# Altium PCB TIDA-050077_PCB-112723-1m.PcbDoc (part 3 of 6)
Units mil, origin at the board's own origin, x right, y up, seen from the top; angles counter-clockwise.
Board outline 3780 x 7750 mil, 16 copper layers (Top Layer, L2-Powet 1, L3-Power 2, L4-Power 3, L5-Power 4, L6-INT 1, L7-INT 2, L8-INT 3, L9-INT 4, L10-INT 5, L11-INT 6, L12-Power 5, L13-Power 6, L14-Power 7, L15-Power 8, Bottom Layer), stack 121.442 mil thick; 381 components, 136 nets, 958 pads, 3470 vias.
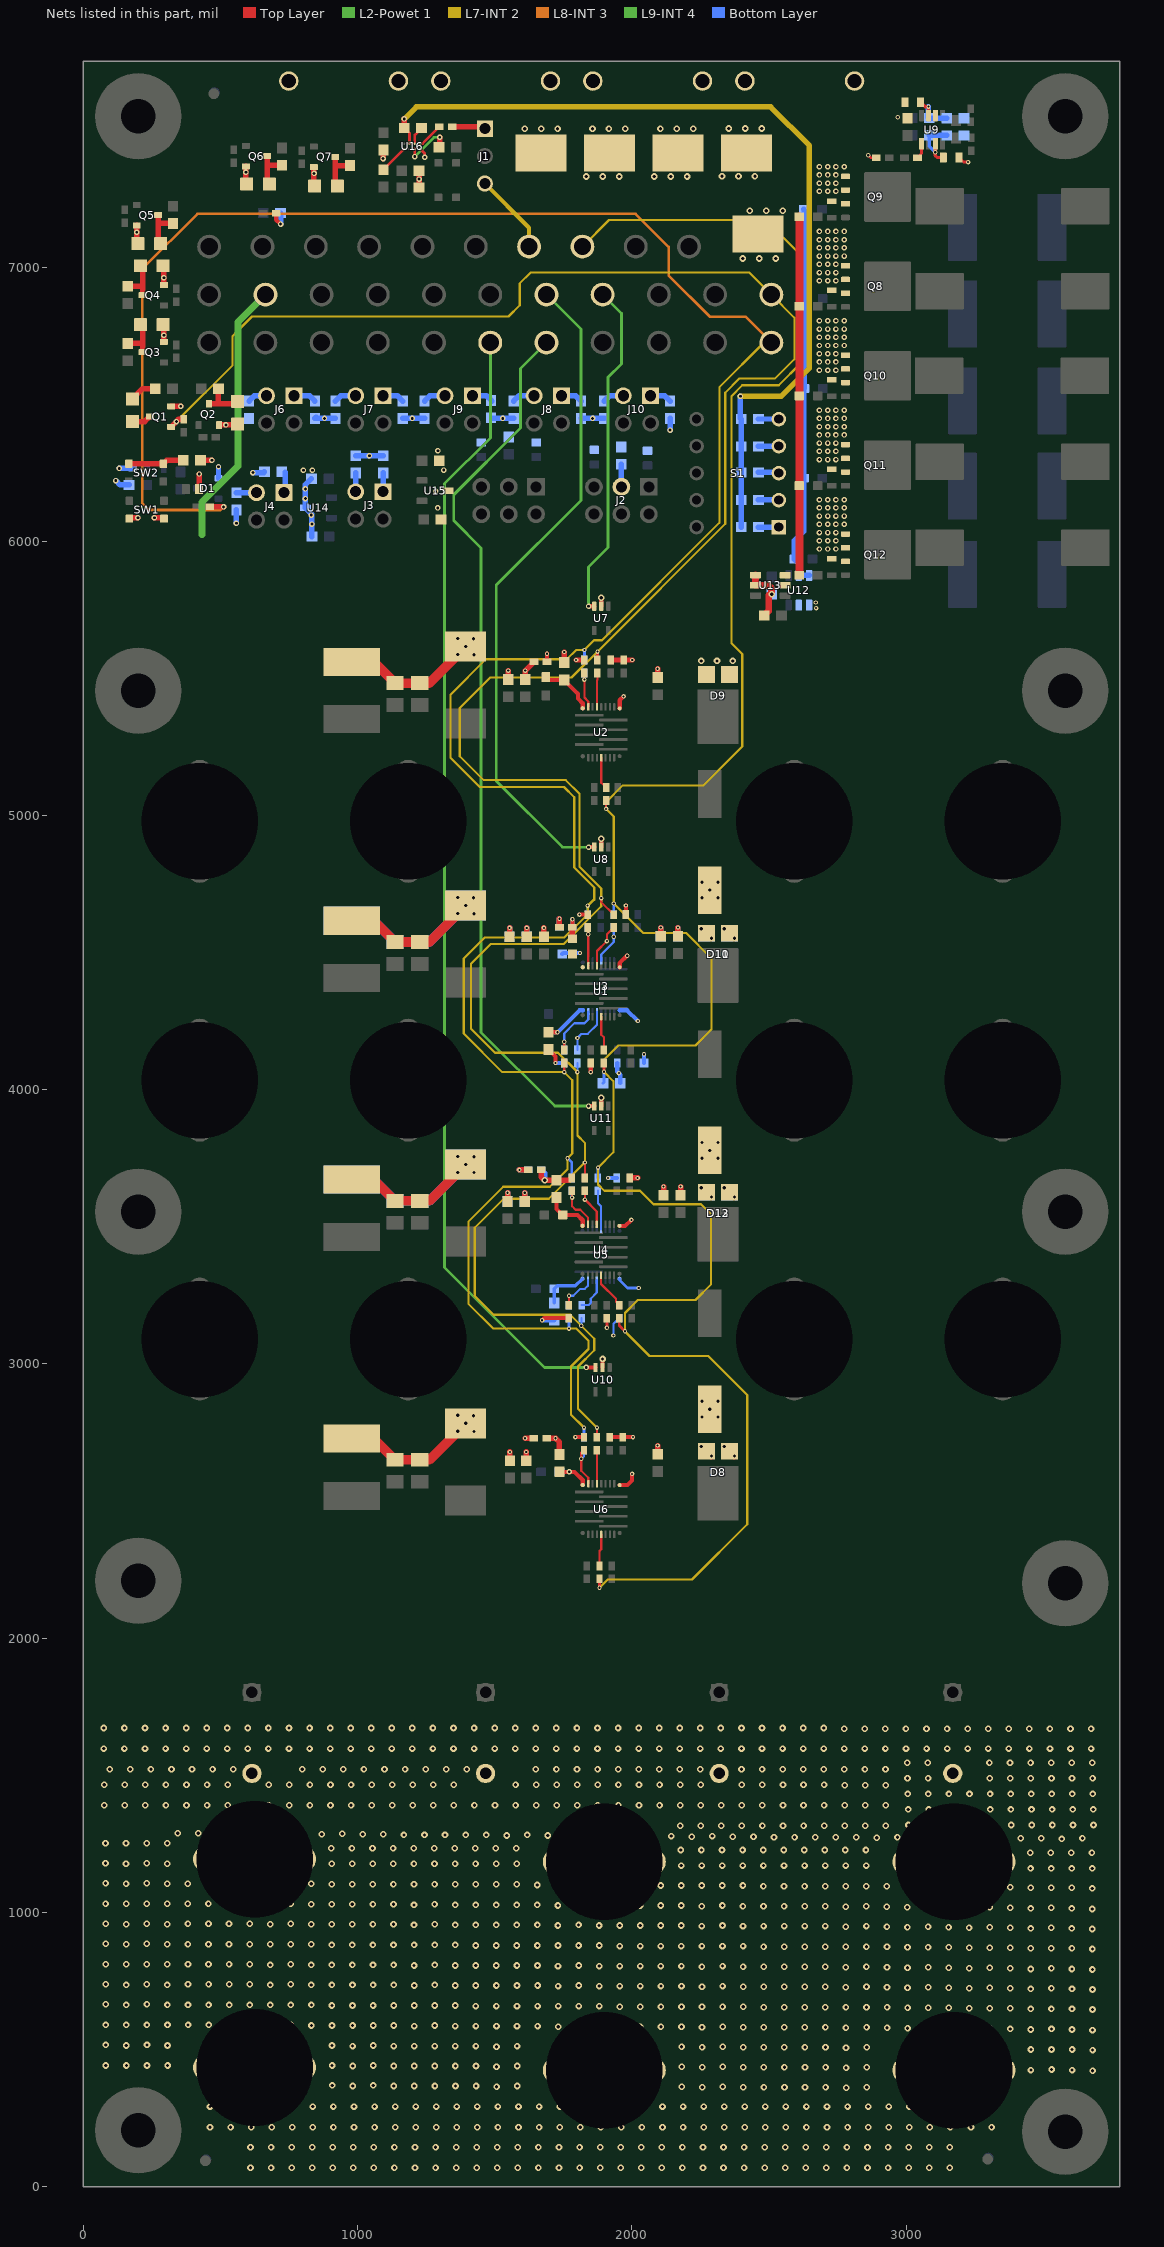
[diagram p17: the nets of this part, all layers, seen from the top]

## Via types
v1: diameter 24, hole 12, Top Layer to Bottom Layer, 2618 vias
v2: diameter 20, hole 10, Top Layer to Bottom Layer, 508 vias
v3: diameter 16, hole 8, Top Layer to Bottom Layer, tented both sides, 135 vias
v4: diameter 24, hole 12.1, Top Layer to Bottom Layer, 125 vias
v5: diameter 20, hole 10, Top Layer to Bottom Layer, tented both sides, 84 vias

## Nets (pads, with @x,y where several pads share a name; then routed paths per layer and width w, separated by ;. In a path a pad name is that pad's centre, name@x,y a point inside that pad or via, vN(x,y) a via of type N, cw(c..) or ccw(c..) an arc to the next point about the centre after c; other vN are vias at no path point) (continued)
NetCD3_1: CD3.1 J2.3 | length 82.1
  Bottom Layer w20: CD3.1@1961.46,6280.53 1961.46,6199.28 J2.3@1962.04,6198.69
NetCT1_1: CT1.1 U16.C2 | length 67.2
  Top Layer w10: U16.C2@1208.73,7449.78 1208.73,7482 CT1.1@1233.45,7506.72
NetCT1_2: CT1.2 R52.1 R53.1 R56.1 R57.1 R58.1 U16.B2 | length 3234.4
  Top Layer w10: CT1.2@1170.46,7506.72 1189.04,7488.14 U16.B2@1189.04,7449.78
  Top Layer w20: CT1.2@1170.46,7506.72 v5(1170.46,7540.09)
  L7-INT 2 w20: v5(1170.46,7540.09) 1214.27,7583.9 2505.86,7583.9 2647.06,7442.69 2647.06,6631.08 2544.42,6528.44 v5(2395.98,6528.44)
  Bottom Layer w20: v5(2395.98,6528.44) 2395.98,6448.59 R58.1@2398.73,6445.84 R57.1@2398.73,6345.84 R56.1@2398.73,6250.84 R53.1@2398.73,6150.84 R52.1@2398.73,6051.59
NetDG1_1: DG1.1 Q1.3 | length 71.2
  Top Layer w20: DG1.1@178.48,6436.38 223.7,6436.38 Q1.3@242.08,6454.76
NetDG1_2: DG1.2 R8.1 | length 99
  Top Layer w20: DG1.2@178.48,6519.06 215.98,6556.56 R8.1@261.98,6556.56
NetDR1_2: DR1.2 Q2.3 R9.2 | length 161.7
  Top Layer w20: Q2.3@458.98,6502.28 490.09,6502.28 ; R9.2@492.58,6556.19 492.58,6504.77 490.09,6502.28 ; DR1.2@562.48,6510.14 554.62,6502.28 490.09,6502.28
NetDR2_2: DR2.2 Q3.3 R7.2 | length 157.2
  Top Layer w20: R7.2@162.04,6721.26 215.83,6721.26 215.95,6721.37 ; DR2.2@208.09,6789.76 215.95,6781.9 215.95,6721.37 ; Q3.3@215.95,6689.76 215.95,6721.37
NetDR3_2: DR3.2 Q4.3 R1.2 | length 165.3
  Top Layer w20: R1.2@162.04,6929.76 214.34,6929.76 215.95,6931.37 ; DR3.2@208.09,7004.76 215.95,6996.9 215.95,6931.37 ; Q4.3@215.95,6897.26 215.95,6931.37
NetDR4_2: DR4.2 Q5.3 R2.2 | length 162.4
  Top Layer w20: Q5.3@272.66,7189.27 272.66,7161.42 ; DR4.2@281.48,7085.43 272.66,7094.25 272.66,7161.42 ; R2.2@326.57,7158.93 275.15,7158.93 272.66,7161.42
NetDR5_2: DR5.2 Q6.3 R3.2 | length 161.1
  Top Layer w20: Q6.3@670.46,7404.33 670.46,7376.01 ; DR5.2@678.32,7302.35 670.46,7310.21 670.46,7376.01 ; R3.2@724.38,7371.19 675.28,7371.19 670.46,7376.01
NetDR6_2: DR6.2 Q7.3 R4.2 | length 164.5
  Top Layer w20: Q7.3@918.47,7401.46 918.47,7368.23 ; DR6.2@926.33,7294.84 918.47,7302.7 918.47,7368.23 ; R4.2@972.38,7369.96 920.2,7369.96 918.47,7368.23
NetJ1_1: J1.1 RZ4.2 | length 121.7
  Top Layer w20: RZ4.2@1345.58,7511.72 1456.96,7511.72 J1.1@1464.28,7504.41
NetJ1_3: J1.3 TP8.1 | length 296.6
  L7-INT 2 w15: J1.3@1464.28,7304.41 1625.4,7143.29 TP8.1@1625.4,7074.5
NetJ3_1: J3.1 r51.2 | length 68.5
  Bottom Layer w20: J3.1@1093.21,6180.62 r51.2@1093.21,6249.13
NetJ3_3: J3.3 R54.2 | length 68.5
  Bottom Layer w20: J3.3@993.21,6180.62 R54.2@993.21,6249.13
NetJ4_1: J4.1 RL1.2 | length 76.2
  Bottom Layer w20: J4.1@731.41,6177.18 735.57,6181.34 RL1.2@735.57,6251.65
NetJ4_3: J4.3 RL2.2 | length 73.2
  Bottom Layer w20: RL2.2@558.21,6177.18 J4.3@631.41,6177.18
NetJ6_1: J6.1 R61.2 | length 79.9
  Bottom Layer w20: J6.1@772.53,6530.62 824.7,6530.62 R61.2@844.33,6510.99
NetJ6_3: J6.3 R62.2 | length 76.3
  Bottom Layer w20: R62.2@604.33,6510.99 623.96,6530.62 J6.3@672.53,6530.62
NetJ7_1: J7.1 R66.2 | length 79.3
  Bottom Layer w20: J7.1@1093.21,6530.62 1144.7,6530.62 R66.2@1164.33,6510.99
NetJ7_3: J7.3 R67.2 | length 82
  Bottom Layer w20: R67.2@919.33,6510.99 938.96,6530.62 J7.3@993.21,6530.62
NetJ8_1: J8.1 R71.2 | length 79.3
  Bottom Layer w20: J8.1@1743.66,6530.62 1795.18,6530.62 R71.2@1814.81,6510.99
NetJ8_3: J8.3 R72.2 | length 82.5
  Bottom Layer w20: R72.2@1569.33,6510.99 1588.96,6530.62 J8.3@1643.66,6530.62
NetJ9_1: J9.1 R76.2 | length 79
  Bottom Layer w20: J9.1@1418.43,6530.62 1469.7,6530.62 R76.2@1489.33,6510.99
NetJ9_3: J9.3 R77.2 | length 82.2
  Bottom Layer w20: R77.2@1244.33,6510.99 1263.96,6530.62 J9.3@1318.43,6530.62
NetJ10_1: J10.1 R81.2 | length 78.6
  Bottom Layer w20: J10.1@2068.88,6530.62 2119.7,6530.62 R81.2@2139.33,6510.99
NetJ10_3: J10.3 R82.2 | length 78.2
  Bottom Layer w20: R82.2@1898.82,6510.99 1918.45,6530.62 J10.3@1968.88,6530.62
NetR18_1: R18.1 R19.1 R20.1 R21.1 R22.1 U12.2 U12.3 | length 1396
  Bottom Layer w20: R19.1@2626.85,7210.5 2628.82,7208.52 R18.1@2628.82,6885.07 2629.63,6884.27 R20.1@2629.63,6557.06 2627.73,6555.16 R21.1@2627.73,6230.06 2627.73,6036.96 2592.06,6001.3 R22.1@2592.06,5935.11 2608.8,5918.37 U12.2@2608.8,5875.52 U12.3@2646.21,5875.52
NetR33_1: R33.1 R34.1 R35.1 R36.1 R37.1 U13.2 U13.3 | length 1307.1
  Top Layer w29.53: R37.1@2610.86,5876.37 R36.1@2610.86,6203.15 R35.1@2610.86,6529.93 R33.1@2610.86,6856.72 R34.1@2610.86,7183.5
NetR38_1: R38.1 U16.A1 | length 99.4
  Top Layer w10: R38.1@1099.85,7359.48 1099.85,7360.59 U16.A1@1169.36,7430.09
NetR39_1: R39.1 U16.C1 | length 184.7
  Top Layer w10: v5(1208.73,7403.01) U16.C1@1208.73,7430.09
  Top Layer w20: R39.1@1296.96,7436.72 1299.85,7439.62 v5(1299.85,7472.98)
  L9-INT 4 w10: v5(1208.73,7403.01) 1278.7,7472.98 v5(1299.85,7472.98)
NetR48_1: R48.1 SW2.1 SW2.2 | length 203.2
  Top Layer w20: SW2.1@166.03,6282.78 SW2.2@292.01,6282.78 304.53,6295.3 R48.1@364.02,6295.3
NetR52_2: R52.2 S1.1 | length 73.1
  Bottom Layer w20: R52.2@2461.72,6051.59 S1.1@2534.79,6051.59
NetR53_2: R53.2 S1.2 | length 73.4
  Bottom Layer w20: R53.2@2461.72,6150.84 2533.97,6150.84 S1.2@2534.79,6150.01
NetR56_2: R56.2 S1.3 | length 74.1
  Bottom Layer w20: R56.2@2461.72,6250.84 2532.39,6250.84 S1.3@2534.79,6248.44
NetR57_2: R57.2 S1.4 | length 73.5
  Bottom Layer w20: R57.2@2461.72,6345.84 2533.76,6345.84 S1.4@2534.79,6346.86
NetR58_2: R58.2 S1.5 | length 73.3
  Bottom Layer w20: R58.2@2461.72,6445.84 2534.24,6445.84 S1.5@2534.79,6445.29
NetRZ2_2: RZ2.2 U9.5 | length 63.1
  Top Layer w10: RZ2.2@3036.82,7394.6 3056.24,7414.02 U9.5@3056.24,7449.64
NetRZ4_1: RZ4.1 U16.D2 | length 95.6
  Top Layer w10: U16.D2@1228.41,7449.78 1236.39,7449.78 RZ4.1@1298.33,7511.72
NetTP1_1: TP1.1 U7.3 | length 1235.2
  Top Layer w15: v5(1842.12,5763.19) U7.3@1863.04,5763.19
  L9-INT 4 w10: v5(1842.12,5763.19) 1842.12,5906.36 1913.42,5977.67 1913.42,6598.04 1962.04,6646.66 1962.04,6831.18 TP1.1@1893.73,6899.5
NetTP2_1: TP2.1 U8.3 | length 2411
  Top Layer w15: v5(1842.12,4884.52) U8.3@1863.04,4884.52
  L9-INT 4 w10: TP2.1@1688.73,6899.5 1814.28,6773.95 1814.28,6148.5 1505.65,5839.87 1505.65,5125.55 1746.67,4884.52 v5(1842.12,4884.52)
NetTP3_1: TP3.1 U10.3 | length 4143.9
  Top Layer w15: v5(1833.56,2987.29) U10.3@1867.8,2987.29
  L9-INT 4 w10: TP3.1@1483.73,6724.5 1484.28,6723.95 1484.28,6377.15 1317.13,6210 1317.13,3351.6 1681.44,2987.29 v5(1833.56,2987.29)
NetTP4_1: TP4.1 U11.3 | length 3220.5
  Top Layer w15: v5(1842.12,3940.33) U11.3@1863.04,3940.33
  L9-INT 4 w10: TP4.1@1688.73,6724.5 1594.28,6630.05 1594.28,6413.11 1350.77,6169.59 1350.77,6075.08 1450.31,5975.54 1450.31,4209.42 1719.4,3940.33 v5(1842.12,3940.33)
PG: Q1.1 R44.2 RZ10.2 RZ17.2 RZ24.2 RZ31.2 RZ38.2 RZ45.2 TP17.1 | length 9486.6
  Top Layer w8: RZ31.2@1828.77,3678.28 v3(1828.77,3734.42) ; RZ45.2@1872.89,2733.08 v3(1872.89,2767.89) ; v3(1888.63,4698.9) 1888.63,4684.13 RZ10.2@1934.13,4638.63
  Top Layer w12: RZ17.2@1874.76,5567.04 v3(1874.76,5597.49)
  Top Layer w20: Q1.1@320.09,6417.26 v5(339.21,6436.38) 347.72,6444.89 R44.2@366.08,6444.89
  L7-INT 2 w8: v5(339.21,6436.38) 544.28,6641.45 544.28,6748.83 614.73,6819.28 1550.12,6819.28 1591.63,6860.79 1591.63,6940.45 1631.43,6980.25 2427.98,6980.25 TP17.1@2508.73,6899.5 2592.67,6815.55 2592.67,6664.02 2522.55,6593.9 2392.84,6593.9 2340.77,6541.82 2340.77,6063.5 v3(1874.76,5597.49) 1780.13,5502.86 1483.64,5502.86 1372.57,5391.79 1372.57,5216.14 1459.81,5128.9 1759.28,5128.9 1809.66,5078.52 1809.66,4812.52 1888.63,4733.55 v3(1888.63,4698.9) 1888.63,4668.73 1751.57,4531.67 1485.55,4531.67 1413.58,4459.7 1413.58,4222.8 1501.24,4135.13 1730.84,4135.13 v3(1801.66,4064.31) 1801.66,3833.32 1828.77,3806.21 v3(1828.77,3734.42) 1696.78,3602.43 1533.29,3602.43 1427.22,3496.36 1427.22,3248.12 1495.8,3179.54 1775.38,3179.54 v3(1815.91,3139) 1862.98,3091.94 1862.98,3049.77 1803.99,2990.78 1803.99,2836.78 v3(1872.89,2767.89)
  Bottom Layer w8: v3(1801.66,4064.31) RZ24.2@1801.66,4097.6 ; v3(1815.91,3139) 1816.55,3139.63 RZ38.2@1816.55,3167.28
PG_0: RZ10.1 U1.19 | length 165
  Top Layer w7.87: U1.19@1872.89,4451.8 1872.89,4505.77 v3(1909.07,4541.95) 1909.07,4566.33 RZ10.1@1934.13,4591.39
PG_1: RZ17.1 U2.19 | length 124.6
  Top Layer w8: U2.19@1872.89,5396 1872.89,5493.55 1874.76,5495.42 RZ17.1@1874.76,5519.8
PG_2: RZ24.1 U3.19 | length 182.3
  Bottom Layer w8: RZ24.1@1801.66,4144.84 v3(1801.66,4188.72) 1816.51,4203.57 1838.98,4203.57 1872.89,4237.47 U3.19@1872.89,4284.48
PG_3: RZ31.1 U4.19 | length 140.2
  Top Layer w8: RZ31.1@1828.77,3631.03 1828.77,3599.68 v3(1829.02,3599.42) 1872.19,3556.26 U4.19@1872.19,3508.81
PG_4: RZ38.1 U5.19 | length 129.5
  Bottom Layer w8: RZ38.1@1816.55,3214.52 1842.28,3214.52 1850.05,3222.3 1850.05,3238.26 1872.19,3260.4 U5.19@1872.19,3305.85
PG_5: RZ45.1 U6.19 | length 122.5
  Top Layer w8: U6.19@1872.89,2563.41 1872.89,2598.6 1872.83,2598.6 1872.83,2632.5 1872.89,2632.56 RZ45.1@1872.89,2685.83
PGND: C6.2 C7.2 C10.1 C11.1 C12.1 C13.1 C14.1 C19.2 C20.2 C21.2 C22.2 C23.2 C24.2 C31.2 C32.2 C33.2 C34.2 C35.2 C36.2 C37.2 C38.2 C39.2 C40.2 C41.2 C42.2 C43.2 C44.2 C45.2 C46.2 C47.2 C48.2 C49.2 C50.2 C51.2 C53.2 C54.2 C55.2 C57.2 C58.2 C59.2 C61.2 C62.2 C63.2 C65.2 C66.2 C67.2 CO1.2 CO2.2 CO3.2 CO4.2 CO5.2 CO6.2 CO7.2 D2.2 D3.2 D4.2 D5.2 D6.2 D7.2 D8.1 D8.2 D9.1 D9.2 D10.1 D10.2 D11.1 D11.2 D12.1 D12.2 D13.1 D13.2 Q8.1 Q8.2 Q8.3 Q9.1 Q9.2 Q9.3 Q10.1 Q10.2 Q10.3 Q11.1 Q11.2 Q11.3 Q12.1 Q12.2 Q12.3 RZ5.2 RZ13.2 RZ20.2 RZ27.2 RZ34.2 RZ41.2 T3.1 T4.1 T11.1 T12.1 T13.1 T16.1 T17.1 TP15.1 U12.4 U12.5 U13.4 U13.5 | length 5426.3
  Top Layer w20: C62.2@1547.08,3592.68 v3(1547.08,3624.63) ; C49.2@1549.28,5496.22 v3(1549.28,5528.18) ; C21.2@1554.28,4558 v3(1554.28,4589.96) ; C65.2@1555.44,2647.15 v3(1555.44,2679.1) ; v3(1589.89,3707.77) RZ27.2@1621.84,3707.77 ; C58.2@1609.26,3592.68 v3(1609.26,3624.63) ; v3(1610.74,2728.9) RZ41.2@1642.69,2728.9 ; C50.2@1611.52,5496.22 v3(1611.52,5528.18) ; C50.2@1611.52,5513.02 v3(1611.52,5528.18) ; C66.2@1615.01,2647.15 v3(1615.01,2679.1) ; C19.2@1616.81,4558 v3(1616.81,4589.96) ; RZ13.2@1643.24,5559.9 v3(1611.52,5528.18) ; C20.2@1679.34,4558 v3(1679.34,4589.96) ; RZ5.2@1736.1,4591.62 v3(1736.1,4623.58) ; C67.2@2094.18,2670.48 v3(2094.18,2702.43) ; C51.2@2094.18,5503.07 v3(2094.18,5535.02) ; C23.2@2105.75,4559.42 v3(2105.75,4591.37) ; C59.2@2115.7,3615.05 v3(2115.7,3647) ; C24.2@2168.28,4559.42 v3(2168.28,4591.37) ; C63.2@2177.9,3615.05 v3(2177.9,3647)
  Top Layer w25: v1(2253.44,2698.63) 2270.41,2681.66 D8.1@2272.35,2681.66 D8.1@2289.69,2664.32 ; v1(2253.44,3642.83) 2270.41,3625.85 D13.1@2272.35,3625.85 D13.1@2289.69,3608.51 ; v1(2253.44,4587.02) 2270.41,4570.05 D11.1@2272.35,4570.05 D11.1@2289.69,4552.71 ; v1(2337.29,2698.63) 2354.27,2681.66 D8.2@2356.21,2681.66 D8.2@2373.55,2664.32 ; v1(2337.29,3642.83) 2354.27,3625.85 D13.2@2356.21,3625.85 D13.2@2373.55,3608.51 ; v1(2337.29,4587.02) 2354.27,4570.05 D11.2@2356.21,4570.05 D11.2@2373.55,4552.71 ; U13.4@2450.85,5876.89 U13.5@2450.85,5839.49 2499.24,5839.49 2509.28,5829.46 2509.28,5812.13 2499.24,5802.1 2499.24,5745.91 C7.2@2482.83,5729.5
  Top Layer w35: C42.2@978.28,2739.6 1047.35,2739.6 C45.2@1136.71,2650.25 C46.2@1226.71,2650.25 1261.78,2650.25 v1(1365.72,2754.18) 1365.72,2755.17 v1(1393.92,2783.37) ; C33.2@978.28,3683.8 1047.35,3683.8 C39.2@1136.71,3594.44 1261.78,3594.44 v1(1365.72,3698.38) 1365.72,3699.37 v1(1393.92,3727.57) ; C32.2@978.28,4627.99 1047.35,4627.99 C37.2@1136.71,4538.64 1261.78,4538.64 v1(1365.72,4642.57) 1365.72,4643.57 v1(1393.92,4671.77) ; C31.2@978.28,5572.19 1047.35,5572.19 C35.2@1136.71,5482.83 1261.78,5482.83 v1(1365.72,5586.77) 1365.72,5587.76 v1(1393.92,5615.96)
  L2-Powet 1 w25: 432.86,6023.9 432.86,6142.4 564.08,6273.62 564.08,6799.36 TP15.1@664.22,6899.5
  Bottom Layer w20: C61.2@1547.08,3592.68 v3(1547.08,3624.63) ; C54.2@1554.28,4558 v3(1554.28,4589.96) ; v3(1589.89,3707.77) RZ34.2@1621.84,3707.77 ; C57.2@1609.26,3592.68 v3(1609.26,3624.63) ; C53.2@1616.81,4558 v3(1616.81,4589.96) ; RZ20.2@1736.1,4591.62 v3(1736.1,4623.58) ; C22.2@2105.75,4559.42 v3(2105.75,4591.37) ; C55.2@2168.28,4559.42 v3(2168.28,4591.37)
  Bottom Layer w35: C40.2@978.28,3683.8 1047.35,3683.8 C43.2@1136.71,3594.44 1261.78,3594.44 v1(1365.72,3698.38) 1365.72,3699.37 v1(1393.92,3727.57) ; C41.2@978.28,4627.99 1047.35,4627.99 C47.2@1136.71,4538.64 1261.79,4538.64 v1(1365.72,4642.57) 1365.72,4643.57 v1(1393.92,4671.77)
  other v1: 609.42,68.9 684.42,68.9 759.42,68.9 834.42,68.9 909.42,68.9 984.42,68.9 1059.42,68.9 1134.42,68.9 1209.42,68.9 1284.42,68.9 1359.42,68.9 1434.42,68.9 1509.42,68.9 1584.42,68.9 1659.42,68.9 1734.42,68.9 1809.43,68.9 1884.43,68.9 1959.43,68.9 2034.43,68.9 2109.43,68.9 2184.43,68.9 2259.43,68.9 2334.43,68.9 2409.43,68.9 2484.43,68.9 2559.43,68.9 2634.43,68.89 2709.43,68.89 2784.43,68.89 2859.43,68.89 2934.43,68.89 3009.43,68.89 3084.43,68.89 3159.43,68.89 609.42,143.9 684.42,143.9 759.42,143.9 834.42,143.9 909.42,143.9 984.42,143.9 1059.42,143.9 1134.42,143.9 1209.42,143.9 1284.42,143.9 1359.42,143.9 1434.42,143.9 1509.42,143.9 1584.42,143.9 1659.42,143.9 1734.42,143.9 1809.42,143.9 1884.43,143.9 1959.43,143.9 2034.43,143.9 2109.43,143.9 2184.43,143.9 2259.43,143.9 2334.43,143.9 2409.43,143.9 2484.43,143.9 2559.43,143.9 2634.43,143.89 2709.43,143.89 2784.43,143.89 2859.43,143.89 2934.43,143.89 3009.43,143.89 3084.43,143.89 3159.43,143.89 461.82,216.87 536.82,216.87 611.82,216.87 686.83,216.87 761.83,216.87 836.83,216.87 911.83,216.87 986.83,216.87 1061.83,216.87 1136.83,216.87 1211.83,216.87 1286.83,216.87 1361.83,216.87 1436.83,216.87 1511.83,216.87 1586.83,216.87 1661.83,216.87 1736.83,216.87 1811.83,216.87 1886.83,216.87 1961.83,216.87 2036.83,216.87 2111.83,216.87 2186.83,216.87 2261.83,216.87 2336.83,216.87 2411.83,216.87 2486.83,216.87 2561.83,216.87 2636.83,216.87 2711.83,216.87 2786.83,216.87 2861.83,216.87 2936.83,216.87 3011.83,216.87 3086.83,216.87 3161.83,216.87 3236.83,216.87 3311.83,216.87 461.82,291.87 536.82,291.87 611.82,291.87 686.82,291.87 761.83,291.87 836.83,291.87 911.83,291.87 986.83,291.87 1061.83,291.87 1136.83,291.87 1211.83,291.87 1286.83,291.87 1361.83,291.87 1436.83,291.87 1511.83,291.87 1586.83,291.87 1661.83,291.87 1736.83,291.87 1811.83,291.87 1886.83,291.87 1961.83,291.87 2036.83,291.87 2111.83,291.87 2186.83,291.87 2261.83,291.87 2336.83,291.87 2411.83,291.87 2486.83,291.87 2561.83,291.87 2636.83,291.87 2711.83,291.87 2786.83,291.87 2861.83,291.87 2936.83,291.87 3011.83,291.87 3086.83,291.87 3161.83,291.87 3236.83,291.87 3311.83,291.87 2781.43,360.57 2256.62,362.67 2406.62,362.67 2481.62,362.67 2556.62,362.67 2631.62,362.67 2706.62,362.67 2856.63,362.67 1506.82,364.77 2181.82,364.77 2331.82,364.77 982.02,366.87 1132.02,366.87 1207.02,366.87 1282.02,366.87 1357.02,366.87 1432.02,366.87 1582.02,366.87 907.22,368.97 1057.22,368.97 3680.23,422.98 3455.43,425.08 3605.43,425.08 3530.63,427.18 2781.23,433.47 2256.42,435.57 2406.42,435.57 2481.42,435.57 2556.42,435.57 2631.43,435.57 2706.43,435.57 2856.43,435.57 1506.62,437.67 2181.62,437.67 2331.62,437.67 981.82,439.77 1131.82,439.77 1206.82,439.77 1281.82,439.77 1356.82,439.77 1431.82,439.77 1581.82,439.77 82.02,441.87 157.02,441.87 232.02,441.87 307.02,441.87 907.02,441.87 1057.02,441.87 3680.23,497.98 3455.43,500.08 3530.43,500.08 3605.43,500.08 2781.03,506.37 2256.22,508.47 2406.22,508.47 2481.22,508.47 2556.23,508.47 2631.23,508.47 2706.23,508.47 2856.23,508.47 1506.42,510.57 2181.42,510.57 2331.42,510.57 981.62,512.67 1131.62,512.67 1206.62,512.67 1281.62,512.67 1356.62,512.67 1431.62,512.67 1581.62,512.67 156.82,514.77 306.82,514.77 906.82,514.77 1056.82,514.77 82.02,516.87 232.02,516.87 3680.03,570.88 3455.23,572.98 3605.23,572.98 3230.43,575.08 3380.43,575.08 3530.43,575.08 3005.63,577.18 3155.63,577.18 3305.63,577.18 2780.83,579.27 2930.83,579.27 3080.83,579.28 2256.02,581.37 2406.02,581.37 2481.02,581.37 2556.03,581.37 2631.03,581.37 2706.03,581.37 2856.03,581.37 1731.22,583.47 1881.22,583.47 1956.22,583.47 2031.22,583.47 2106.22,583.47 2181.22,583.47 2331.22,583.47 1206.42,585.57 1356.42,585.57 1431.42,585.57 1506.42,585.57 1581.42,585.57 1656.42,585.57 1806.42,585.57 681.62,587.67 831.62,587.67 906.62,587.67 981.62,587.67 1056.62,587.67 1131.62,587.67 1281.62,587.67 81.82,589.77 156.82,589.77 231.82,589.77 306.82,589.77 381.82,589.77 456.82,589.77 531.82,589.77 606.82,589.77 756.82,589.77 3680.03,645.88 3455.23,647.98 3530.23,647.98 3605.23,647.98 3230.43,650.08 3305.43,650.08 3380.43,650.08 3005.63,652.18 3080.63,652.18 3155.63,652.18 2480.83,654.27 2555.83,654.27 2630.83,654.27 2705.83,654.27 2780.83,654.27 2855.83,654.27 2930.83,654.27 1956.02,656.37 2031.02,656.37 2106.02,656.37 2181.02,656.37 2256.02,656.37 2331.02,656.37 2406.02,656.37 1431.22,658.47 1506.22,658.47 1581.22,658.47 1656.22,658.47 1731.22,658.47 1806.22,658.47 1881.22,658.47 906.42,660.57 981.42,660.57 1056.42,660.57 1131.42,660.57 1206.42,660.57 1281.42,660.57 1356.42,660.57 156.62,662.67 306.62,662.67 381.62,662.67 456.62,662.67 531.62,662.67 606.62,662.67 681.62,662.67 756.62,662.67 831.62,662.67 81.82,664.77 231.82,664.77 3679.83,718.78 3455.03,720.88 3605.03,720.88 3230.23,722.98 3380.23,722.98 3530.23,722.98 3005.43,725.08 3155.43,725.08 3305.43,725.08 2780.63,727.18 2930.63,727.18 3080.63,727.18 2255.82,729.27 2405.83,729.27 2480.83,729.27 2555.83,729.27 2630.83,729.27 2705.83,729.27 2855.83,729.27 1731.02,731.37 1881.02,731.37 1956.02,731.37 2031.02,731.37 2106.02,731.37 2181.02,731.37 2331.02,731.37 1206.22,733.47 1356.22,733.47 1431.22,733.47 1506.22,733.47 1581.22,733.47 1656.22,733.47 1806.22,733.47 156.42,735.57 306.42,735.57 681.42,735.57 831.42,735.57 906.42,735.57 981.42,735.57 1056.42,735.57 1131.42,735.57 1281.42,735.57 81.62,737.67 231.62,737.67 381.62,737.67 456.62,737.67 531.62,737.67 606.62,737.67 756.62,737.67 3679.63,791.68 3454.83,793.78 3604.83,793.78 3230.03,795.88 3380.03,795.88 3530.03,795.88 3005.23,797.98 3155.23,797.98 3305.23,797.98 2780.43,800.08 2930.43,800.08 3080.43,800.08 2255.62,802.17 2405.63,802.17 2480.63,802.17 2555.63,802.17 2630.63,802.17 2705.63,802.18 2855.63,802.18 1730.82,804.27 1880.82,804.27 1955.82,804.27 2030.82,804.27 2105.82,804.27 2180.82,804.27 2330.83,804.27 1206.02,806.37 1356.02,806.37 1431.02,806.37 1506.02,806.37 1581.02,806.37 1656.02,806.37 1806.02,806.37 681.22,808.47 831.22,808.47 906.22,808.47 981.22,808.47 1056.22,808.47 1131.22,808.47 1281.22,808.47 81.42,810.57 156.42,810.57 231.42,810.57 306.42,810.57 381.42,810.57 456.42,810.57 531.42,810.57 606.42,810.57 756.42,810.57 3679.63,866.68 3454.83,868.78 3529.83,868.78 3604.83,868.78 3230.03,870.88 3305.03,870.88 3380.03,870.88 3005.23,872.98 3080.23,872.98 3155.23,872.98 2480.43,875.08 2555.43,875.08 2630.43,875.08 2705.43,875.08 2780.43,875.08 2855.43,875.08 2930.43,875.08 1955.62,877.17 2030.62,877.17 2105.62,877.17 2180.62,877.17 2255.63,877.17 2330.63,877.17 2405.63,877.17 1430.82,879.27 1505.82,879.27 1580.82,879.27 1655.82,879.27 1730.82,879.27 1805.82,879.27 1880.82,879.27 906.02,881.37 981.02,881.37 1056.02,881.37 1131.02,881.37 1206.02,881.37 1281.02,881.37 1356.02,881.37 156.22,883.47 306.22,883.47 381.22,883.47 456.22,883.47 531.22,883.47 606.22,883.47 681.22,883.47 756.22,883.47 831.22,883.47 81.42,885.57 231.42,885.57 3679.43,939.58 3454.63,941.68 3604.63,941.68 3229.83,943.78 3379.83,943.78 3529.83,943.78 3005.03,945.88 3155.03,945.88 3305.03,945.88 2780.23,947.98 2930.23,947.98 3080.23,947.98 2255.43,950.07 2405.43,950.08 2480.43,950.08 2555.43,950.08 2630.43,950.08 2705.43,950.08 2855.43,950.08 1730.62,952.17 1880.62,952.17 1955.62,952.17 2030.62,952.17 2105.62,952.17 2180.63,952.17 2330.63,952.17 1205.82,954.27 1355.82,954.27 1430.82,954.27 1505.82,954.27 1580.82,954.27 1655.82,954.27 1805.82,954.27 156.02,956.37 306.02,956.37 681.02,956.37 831.02,956.37 906.02,956.37 981.02,956.37 1056.02,956.37 1131.02,956.37 1281.02,956.37 81.22,958.47 231.22,958.47 381.22,958.47 456.22,958.47 531.22,958.47 606.22,958.47 756.22,958.47 3679.23,1012.48 3454.43,1014.58 3604.43,1014.58 3229.63,1016.68 3379.63,1016.68 3529.63,1016.68 3004.83,1018.78 3154.83,1018.78 3304.83,1018.78 2780.03,1020.88 2930.03,1020.88 3080.03,1020.88 2255.23,1022.98 2405.23,1022.98 2480.23,1022.98 2555.23,1022.98 2630.23,1022.98 2705.23,1022.98 2855.23,1022.98 1730.42,1025.07 1880.42,1025.07 1955.42,1025.07 2030.43,1025.07 2105.43,1025.07 2180.43,1025.07 2330.43,1025.07 1205.62,1027.17 1355.62,1027.17 1430.62,1027.17 1505.62,1027.17 1580.62,1027.17 1655.62,1027.17 1805.62,1027.17 680.82,1029.27 830.82,1029.27 905.82,1029.27 980.82,1029.27 1055.82,1029.27 1130.82,1029.27 1280.82,1029.27 81.02,1031.37 156.02,1031.37 231.02,1031.37 306.02,1031.37 381.02,1031.37 456.02,1031.37 531.02,1031.37 606.02,1031.37 756.02,1031.37 3679.23,1087.48 3454.43,1089.58 3529.43,1089.58 3604.43,1089.58 3229.63,1091.68 3304.63,1091.68 3379.63,1091.68 3004.83,1093.78 3079.83,1093.78 3154.83,1093.78 2480.03,1095.88 2555.03,1095.88 2630.03,1095.88 2705.03,1095.88 2780.03,1095.88 2855.03,1095.88 2930.03,1095.88 1955.23,1097.97 2030.23,1097.97 2105.23,1097.98 2180.23,1097.98 2255.23,1097.98 2330.23,1097.98 2405.23,1097.98 1655.42,1100.07 1730.42,1100.07 1805.42,1100.07 1880.42,1100.07 905.62,1102.17 980.62,1102.17 1055.62,1102.17 1130.62,1102.17 1205.62,1102.17 1280.62,1102.17 1355.62,1102.17 1430.42,1102.17 1505.42,1102.17 1580.42,1102.17 155.82,1104.27 305.82,1104.27 380.82,1104.27 455.82,1104.27 530.82,1104.27 605.82,1104.27 680.82,1104.27 755.82,1104.27 830.82,1104.27 81.02,1106.37 231.02,1106.37 3454.03,1160.38 3529.03,1160.38 3604.03,1160.38 3679.03,1160.38 2180.03,1170.88 2255.03,1170.88 2330.03,1170.88 2405.03,1170.88 2480.03,1170.88 2555.03,1170.88 2630.03,1170.88 2704.83,1170.88 2779.83,1170.88 2854.83,1170.88 155.62,1177.17 305.62,1177.17 905.42,1177.17 980.42,1177.17 1055.42,1177.17 1130.42,1177.17 1205.42,1177.17 1280.42,1177.17 1355.42,1177.17 1430.22,1177.17 1505.22,1177.17 1580.22,1177.17 80.82,1179.27 230.82,1179.27 3452.88,1217.1 3527.88,1217.1 3602.88,1217.1 3677.88,1217.1 2178.88,1227.6 2253.88,1227.6 2328.88,1227.6 2403.88,1227.6 2478.88,1227.6 2553.88,1227.6 2628.88,1227.6 2703.68,1227.6 2778.68,1227.6 2853.68,1227.6 904.28,1233.9 979.28,1233.9 1054.28,1233.9 1129.28,1233.9 1204.28,1233.9 1279.28,1233.9 1354.28,1233.9 1429.08,1233.9 1504.08,1233.9 1579.08,1233.9 80.62,1252.17 155.62,1252.17 230.62,1252.17 305.62,1252.17 3568.09,1267.91 3193.29,1270 3268.29,1270 3343.29,1270 3418.29,1270 3493.29,1270 3643.29,1270 2893.28,1272.1 3043.29,1272.1 3118.49,1272.1 2518.48,1274.2 2593.48,1274.2 2668.48,1274.2 2743.48,1274.2 2818.48,1274.2 2968.49,1274.2 2218.48,1276.3 2368.48,1276.3 2443.68,1276.3 1843.68,1278.4 1918.68,1278.4 1993.68,1278.4 2068.68,1278.4 2143.68,1278.4 2293.68,1278.4 1543.68,1280.5 1693.68,1280.5 1768.88,1280.5 1168.88,1282.6 1243.88,1282.6 1318.88,1282.6 1393.88,1282.6 1468.88,1282.6 1618.88,1282.6 868.88,1284.7 1018.88,1284.7 1094.08,1284.7 494.08,1286.8 569.08,1286.8 644.08,1286.8 719.08,1286.8 794.08,1286.8 944.08,1286.8 344.08,1288.9 419.28,1288.9 2176.35,1315.62 2251.35,1315.62 2326.35,1315.62 2401.35,1315.62 2476.35,1315.62 2551.35,1315.62 2626.35,1315.62 2701.35,1315.62 2776.35,1315.62 2851.35,1315.62 2926.35,1315.62 3008.69,1318.71 3083.69,1318.71 3158.69,1318.71 3233.69,1318.71 3308.69,1318.71 3383.69,1318.71 3458.69,1318.71 3533.69,1318.71 3608.69,1318.71 3683.49,1318.71 3007.54,1375.43 3082.54,1375.43 3157.54,1375.43 3232.54,1375.43 3307.54,1375.43 3382.54,1375.43 3457.54,1375.43 3532.54,1375.43 3607.54,1375.43 3682.34,1375.43 76.15,1390.62 151.15,1390.62 226.15,1390.62 301.15,1390.62 376.15,1390.62 451.15,1390.62 526.15,1390.62 601.15,1390.62 676.15,1390.62 751.15,1390.62 826.15,1390.62 901.15,1390.62 976.15,1390.62 1051.15,1390.62 1126.15,1390.62 1201.15,1390.62 1276.15,1390.62 1351.15,1390.62 1426.15,1390.62 1501.15,1390.62 1576.15,1390.62 1651.15,1390.62 1726.15,1390.62 1801.15,1390.62 1876.15,1390.62 1951.15,1390.62 2026.15,1390.62 2101.15,1390.62 2176.15,1390.62 2251.15,1390.62 2326.15,1390.62 2401.15,1390.62 2476.15,1390.62 2551.15,1390.62 2626.15,1390.62 2701.15,1390.62 2776.15,1390.62 2851.15,1390.62 2926.15,1390.62 3006.4,1432.16 3081.4,1432.16 3156.4,1432.16 3231.4,1432.16 3306.4,1432.16 3381.4,1432.16 3456.4,1432.16 3531.4,1432.16 3606.4,1432.16 3681.2,1432.16 2775.95,1463.52 2850.95,1463.52 2925.95,1463.52 76.15,1465.62 151.15,1465.62 226.15,1465.62 301.15,1465.62 376.15,1465.62 451.15,1465.62 526.15,1465.62 676.15,1465.62 751.15,1465.62 826.15,1465.62 901.15,1465.62 976.15,1465.62 1051.15,1465.62 1126.15,1465.62 1201.15,1465.62 1276.15,1465.62 1351.15,1465.62 1576.15,1465.62 1651.15,1465.62 1726.15,1465.62 1801.15,1465.62 1876.15,1465.62 1951.15,1465.62 2026.15,1465.62 2101.15,1465.62 2176.15,1465.62 2251.15,1465.62 2401.15,1465.62 2476.15,1465.62 2551.15,1465.62 2626.15,1465.62 2701.15,1465.62 3005.26,1488.88 3080.26,1488.88 3305.26,1488.88 3380.26,1488.88 3455.26,1488.88 3530.26,1488.88 3605.26,1488.88 3680.06,1488.88 96.27,1522.35 171.27,1522.35 246.27,1522.35 321.27,1522.35 396.27,1522.35 471.27,1522.35 546.27,1522.35 798.14,1522.35 873.14,1522.35 948.14,1522.35 1023.14,1522.35 1098.14,1522.35 1173.14,1522.35 1248.14,1522.35 1323.14,1522.35 1398.14,1522.35 1650.01,1522.35 1725.01,1522.35 1800.01,1522.35 1875.01,1522.35 1950.01,1522.35 2025.01,1522.35 2100.01,1522.35 2175.01,1522.35 2250.01,1522.35 2400.01,1522.35 2475.01,1522.35 2550.01,1522.35 2625.01,1522.35 2700.01,1522.35 2775.01,1522.35 2850.01,1522.35 2925.01,1522.35 3004.11,1545.6 3079.11,1545.6 3304.12,1545.6 3379.12,1545.6 3454.12,1545.6 3529.12,1545.6 3604.12,1545.6 3678.92,1545.6 74.8,1597.35 149.8,1597.35 224.8,1597.35 299.8,1597.35 374.8,1597.35 449.8,1597.35 524.8,1597.35 599.8,1597.35 674.8,1597.35 749.8,1597.35 824.8,1597.35 899.8,1597.35 974.8,1597.35 1049.8,1597.35 1124.81,1597.35 1199.81,1597.35 1274.81,1597.35 1349.81,1597.35 1424.81,1597.35 1499.81,1597.35 1574.81,1597.35 1649.81,1597.35 1724.81,1597.35 1799.81,1597.35 1874.81,1597.35 1949.81,1597.35 2024.81,1597.35 2099.81,1597.35 2174.81,1597.35 2249.81,1597.35 2324.81,1597.35 2399.81,1597.35 2474.81,1597.35 2549.81,1597.35 2624.81,1597.35 2699.81,1597.35 2774.81,1597.35 2849.81,1597.35 2924.81,1597.35 2999.81,1597.34 3074.81,1597.34 3149.81,1597.34 3224.81,1597.34 3299.81,1597.34 3374.81,1597.34 3449.81,1597.34 3524.81,1597.34 3599.81,1597.34 3674.81,1597.34 2774.61,1670.25 2849.61,1670.25 2924.61,1670.25 2999.61,1670.25 3074.61,1670.25 3149.61,1670.25 3224.61,1670.25 3299.61,1670.24 3374.61,1670.24 3449.61,1670.24 3524.61,1670.24 3599.61,1670.24 3674.61,1670.24 74.8,1672.35 149.8,1672.35 224.8,1672.35 299.8,1672.35 374.8,1672.35 449.8,1672.35 524.8,1672.35 599.8,1672.35 674.8,1672.35 749.8,1672.35 824.8,1672.35 899.8,1672.35 974.8,1672.35 1049.81,1672.35 1124.81,1672.35 1199.81,1672.35 1274.81,1672.35 1349.81,1672.35 1424.81,1672.35 1499.81,1672.35 1574.81,1672.35 1649.81,1672.35 1724.81,1672.35 1799.81,1672.35 1874.81,1672.35 1949.81,1672.35 2024.81,1672.35 2099.81,1672.35 2174.81,1672.35 2249.81,1672.35 2324.81,1672.35 2399.81,1672.35 2474.81,1672.35 2549.81,1672.35 2624.81,1672.35 2699.81,1672.35 2290.27,2664.32 2374.13,2664.32 1424.39,2753.66 2256.2,2806.3 2313.99,2806.3 1423.02,2811.46 1365.72,2812.65 2284.28,2834.5 2256.2,2863.6 2313.99,2863.6 2290.27,3608.51 2374.13,3608.51 1424.39,3697.86 2256.2,3750.5 2313.99,3750.5 1424.39,3755.66 1365.72,3756.84 2284.28,3778.7 2256.2,3807.8 2313.99,3807.8 2290.27,4552.71 2374.13,4552.71 1424.4,4642.06 1423.02,4699.85 2256.2,4699.78 2313.99,4699.78 1365.72,4701.04 2284.28,4727.98 2256.2,4757.07 2313.99,4757.07 2252.93,5563.62 2310.73,5563.62 2368.52,5563.62 1424.39,5586.25 1423.02,5644.05 1365.72,5645.24 2510.54,5807.13
  other v2: 2684.28,5971.77 2714.28,5971.77 2744.28,5971.77 2684.28,6001.77 2714.28,6001.77 2744.28,6001.77 2684.28,6031.77 2714.28,6031.77 2744.28,6031.77 2684.28,6061.77 2714.28,6061.77 2744.28,6061.77 2774.28,6061.77 2684.28,6091.77 2714.28,6091.77 2744.28,6091.77 2774.28,6091.77 2684.28,6121.77 2714.28,6121.77 2744.28,6121.77 2774.28,6121.77 2684.28,6151.77 2714.28,6151.77 2744.28,6151.77 2774.28,6151.77 2684.28,6297.9 2714.28,6297.9 2744.28,6297.9 2684.28,6327.9 2714.28,6327.9 2744.28,6327.9 2684.28,6357.9 2714.28,6357.9 2744.28,6357.9 2684.28,6387.9 2714.28,6387.9 2744.28,6387.9 2774.28,6387.9 2684.28,6417.9 2714.28,6417.9 2744.28,6417.9 2774.28,6417.9 2684.28,6447.9 2714.28,6447.9 2744.28,6447.9 2774.28,6447.9 2684.28,6477.9 2714.28,6477.9 2744.28,6477.9 2774.28,6477.9 2684.28,6623.9 2714.28,6623.9 2744.28,6623.9 2684.28,6653.9 2714.28,6653.9 2744.28,6653.9 2684.28,6683.9 2714.28,6683.9 2744.28,6683.9 2684.28,6713.9 2714.28,6713.9 2744.28,6713.9 2774.28,6713.9 2684.28,6743.9 2714.28,6743.9 2744.28,6743.9 2774.28,6743.9 2684.28,6773.9 2714.28,6773.9 2744.28,6773.9 2774.28,6773.9 2684.28,6803.9 2714.28,6803.9 2744.28,6803.9 2774.28,6803.9 2684.28,6949.9 2714.28,6949.9 2744.28,6949.9 2684.28,6979.9 2714.28,6979.9 2744.28,6979.9 2684.28,7009.9 2714.28,7009.9 2744.28,7009.9 2684.28,7039.9 2714.28,7039.9 2744.28,7039.9 2774.28,7039.9 2684.28,7069.9 2714.28,7069.9 2744.28,7069.9 2774.28,7069.9 2684.28,7099.9 2714.28,7099.9 2744.28,7099.9 2774.28,7099.9 2684.28,7129.9 2714.28,7129.9 2744.28,7129.9 2774.28,7129.9 2684.28,7275.9 2714.28,7275.9 2744.28,7275.9 2684.28,7305.9 2714.28,7305.9 2744.28,7305.9 2684.28,7335.9 2714.28,7335.9 2744.28,7335.9 2684.28,7365.9 2714.28,7365.9 2744.28,7365.9 2774.28,7365.9
  other v3: 2671.94,5756.12 2670.8,5776.9
QGND: C1.1 C3.2 C4.1 C5.1 C8.2 C9.2 C15.2 C16.2 C17.2 C18.1 C25.2 C26.2 C27.2 C28.2 C29.2 C30.2 C52.1 C56.1 C60.1 C64.1 C68.1 CD1.2 CD2.2 CD3.2 CF1.2 CM1.1 CTEMP1.2 D1.1 DR1.1 DR2.1 DR3.1 DR4.1 DR5.1 DR6.1 G1.1 G1.2 G2.1 G2.2 G3.1 G3.2 G4.1 G4.2 Q1.2 Q2.2 Q3.2 Q4.2 Q5.2 Q6.2 Q7.2 QGND1.1 QGND2.1 QGND3.1 QGND4.1 QGND5.1 R15.1 R16.1 R17.1 R40.2 R45.1 R47.1 R48.2 R50.1 r51.1 R54.1 R55.1 R60.1 R61.1 R62.1 R63.1 R65.1 R66.1 R67.1 R68.1 R70.1 R71.1 R72.1 R73.1 R75.1 R76.1 R77.1 R78.1 R80.1 R81.1 R82.1 RL1.1 RL2.1 RM1.2 RM2.2 RM3.2 RM4.2 RM5.2 RZ5.1 RZ13.1 RZ20.1 RZ27.1 RZ34.1 RZ41.1 SW1.1 SW1.2 U1.14 U2.14 U3.14 U4.14 U5.14 U6.14 U7.2 U8.2 U9.2 U10.2 U11.2 U14.3 U15.3 U16.D1 | length 3664.7
  Top Layer w10: U16.D1@1228.41,7430.09 1244.85,7413.65 v5(1244.85,7400.28) ; R73.1@1909.19,3167.28 1909.19,3132.19 v3(1909.28,3132.1) ; v3(2862.25,7407.48) 2870.82,7398.92 C3.2@2891.64,7398.92 ; R15.1@3193.07,7399.47 3209.8,7382.75 v3(3226.43,7382.75)
  Top Layer w15: CF1.2@703.18,7196.75 703.17,7172.5 v5(718.92,7156.75) ; v3(1672.8,3159.31) 1680.77,3167.28 R75.1@1770.85,3167.28 ; RZ13.1@1690.49,5559.9 v3(1690.49,5590.04) ; C56.1@1695.95,4146.45 1721.76,4120.64 v3(1721.76,4097.6) ; RZ5.1@1783.34,4591.62 v3(1783.34,4621.76) ; v3(1794.38,2733.08) R80.1@1825.64,2733.08 ; v3(1808.87,4638.63) R50.1@1839.01,4638.63 ; v3(1850.05,4064.13) R63.1@1850.05,4097.6 ; U11.2@1888.63,3940.33 v1(1888.63,3971.05) ; U8.2@1888.63,4884.52 v1(1888.63,4915.24) ; U7.2@1888.63,5763.19 v1(1888.63,5793.91) ; U10.2@1893.39,2987.29 v1(1893.39,3018.01) ; R78.1@1920.13,2733.08 RM5.2@1966.85,2733.08 v3(2004.49,2733.08) ; U6.14@1955.81,2558.24 1984.74,2558.24 2000.86,2574.37 v3(2000.86,2599.08) ; U4.14@1955.81,3502.44 1975.35,3502.44 v3(1998.33,3525.42) ; U1.14@1955.81,4446.64 1955.81,4461.29 v3(1983.01,4488.49) ; U2.14@1955.81,5390.83 1955.81,5420.24 v3(1969.96,5434.39) ; R47.1@1978.24,4638.75 v3(1978.24,4671.77)
  Top Layer w20: SW1.2@168.04,6082.61 170.73,6085.3 v5(199.02,6085.3) ; Q5.2@194.66,7151.77 194.66,7089.57 DR4.1@198.8,7085.43 ; v5(259.02,6085.3) 291.33,6085.3 SW1.1@294.02,6082.61 ; DR2.1@290.77,6789.76 293.95,6786.58 Q3.2@293.95,6727.26 ; DR3.1@290.77,7004.76 293.95,7001.58 Q4.2@293.95,6934.76 ; Q1.2@320.09,6492.26 v5(355.09,6492.26) ; C27.2@421.26,6190.3 419.02,6192.55 423.03,6196.55 v5(423.03,6245.3) ; R48.2@427.01,6295.3 v5(469.02,6295.3) ; Q2.2@496.48,6424.27 v5(520.09,6424.27) 559.29,6424.27 DR1.1@562.48,6427.46 ; Q6.2@592.46,7366.83 592.46,7305.54 DR5.1@595.65,7302.35 ; Q7.2@840.47,7363.96 840.47,7298.02 DR6.1@843.65,7294.84 ; v5(1092.73,7395.4) 1092.73,7427.37 1093.35,7427.99 C17.2@1094.85,7426.49 ; C18.1@1224.24,7290.26 v5(1224.24,7320.8) R40.2@1224.24,7351.34 R40.2@1228.41,7355.51 ; RZ27.1@1669.09,3707.77 1669.09,3682.6 v1(1682.04,3669.65) C60.1@1725.62,3669.65 1772.7,3669.65 R70.1@1781.34,3678.28 ; RZ41.1@1689.94,2728.9 v3(1721.89,2728.9) 1735.88,2714.91 C68.1@1735.88,2669.55 ; C52.1@1753.35,5557.4 v3(1753.35,5596.08) ; C25.2@1783.34,4550.13 RZ5.1@1783.34,4591.62 ; v3(1796.75,5567.04) R60.1@1827.2,5567.04 ; R55.1@1922.32,5567.04 RM1.2@1969.88,5567.04 v3(2001.84,5567.04) ; RM3.2@1991.91,3678.28 v3(2020.96,3678.28)
  Bottom Layer w8: v3(1932.65,3103.9) 1932.65,3145.35 RM4.2@1954.58,3167.28
  Bottom Layer w10: U5.14@1955.11,3311.02 1955.11,3305.81 1984.04,3276.88 v3(2025.12,3276.88)
  Bottom Layer w15: v3(1672.8,3159.31) C64.1@1717.14,3159.31 ; v3(1721.76,4097.6) R65.1@1753.27,4097.6 ; RZ20.1@1783.34,4591.62 v3(1783.34,4621.76) ; v3(1913.63,3678.28) R68.1@1945.62,3678.28 ; RM2.2@1946.84,4097.6 1946.84,4066.77 1958.99,4054.62 1957.84,4053.46 CTEMP1.2@1957.84,4023.9 ; U3.14@1955.81,4289.65 1983.16,4289.65 v3(2022.06,4250.74) ; CM1.1@2044.48,4097.6 v3(2044.48,4129.42)
  Bottom Layer w20: v5(118.25,6221.5) 134.45,6205.3 C26.2@166.8,6205.3 ; v5(130.53,6265.6) R17.1@180.4,6265.6 ; D1.1@492.76,6229.95 v5(492.76,6271.96) ; v5(558.21,6065.62) RL2.1@558.21,6114.19 ; v5(618.21,6250.62) 657.69,6250.62 RL1.1@660.21,6253.15 ; v5(718.92,7156.75) R45.1@718.92,7196.75 ; C9.2@831.71,6228.15 810,6206.44 v5(810,6190.62) v5(810,6155.62) U14.3@810,6122.04 833.51,6098.54 v5(833.51,6062.8) C8.2@833.51,6017.04 ; R61.1@849.25,6452.92 R61.1@844.33,6448 v5(879.33,6448) R67.1@919.33,6448 ; R54.1@993.21,6312.12 v5(1043.21,6312.12) r51.1@1093.21,6312.12 ; R66.1@1164.33,6448 v5(1199.33,6448) R77.1@1244.33,6448 ; R76.1@1489.33,6448 v5(1529.33,6448) R72.1@1569.33,6448 ; RZ34.1@1669.09,3707.77 1682.04,3694.81 v1(1682.04,3669.65) ; R71.1@1814.81,6448 v5(1856.82,6448) R82.1@1898.82,6448 ; v5(2139.33,6405.5) R81.1@2139.33,6448
  other v1: 2405.01,7031.12 2465.01,7031.12 2525.01,7031.12 2430.01,7205.73 2490.01,7205.73 2550.01,7205.73 1834.33,7330.12 1894.33,7330.12 1954.33,7330.12 2081.48,7330.12 2141.48,7330.12 2201.48,7330.12 2328.87,7330.67 2388.87,7330.67 2448.87,7330.67 1609.33,7504.73 1669.33,7504.73 1729.33,7504.73 1856.48,7504.73 1916.48,7504.73 1976.48,7504.73 2104.22,7504.73 2164.22,7504.73 2224.22,7504.73 2353.86,7505.28 2413.86,7505.28 2473.86,7505.28
  other v3: 1952.92,4060.7 2969.62,7546.28
  other v5: 831.23,6095.62 1292.33,6121.63 1284.33,6181.63 802.45,6259.37 835.32,6259.37 1314.33,6259.44 1292.81,6330.17 293.73,6751.14 293.73,6961.37 194.88,7126.55 841.15,7341.38 592.68,7345.53
REF1: C4.2 R13.1 R15.2 U9.7 | length 210.6
  Top Layer w12: U9.7@3107.42,7449.64 3106.49,7448.7 v3(3106.49,7418.88) 3106.49,7406.5 3113.52,7399.47 R15.2@3135.99,7399.47
  Bottom Layer w12: R13.1@3084.77,7480.73 3084.77,7440.6 v3(3106.49,7418.88)
  Bottom Layer w20: R13.1@3084.77,7480.73 3147.65,7480.73 C4.2@3148.3,7480.08
REF2: C5.2 R14.1 R16.2 U9.3 | length 174.5
  Top Layer w12: R16.2@3053.27,7600.87 3069.17,7584.96 v3(3081.76,7584.96) ; U9.3@3081.83,7552 v3@3081.83,7584.96
  Bottom Layer w20: v3(3081.76,7584.96) 3081.76,7546.41 R14.1@3084.77,7543.4 3085.15,7543.01 C5.2@3148.3,7543.01
SWEN: R49.1 RZ9.2 RZ16.2 RZ23.2 RZ30.2 RZ37.2 RZ44.2 TP18.1 | length 10523.6
  Top Layer w10: v3(1753.27,4064.13) RZ23.2@1753.27,4097.6
  Top Layer w20: R49.1@461.26,6125.9 461.93,6125.23 v5(511.08,6125.23)
  L8-INT 3 w10: v5(511.08,6125.23) 500.28,6114.43 239.59,6114.43 214.28,6139.74 214.28,6992.32 415.86,7193.9 2013.43,7193.9 2134.28,7073.05 2134.28,6968.9 2284.28,6818.9 2414.33,6818.9 TP18.1@2508.73,6724.5
  L7-INT 2 w8: v3(1825.64,2767.94) 1778.48,2815.1 1778.48,2990.67 1841.97,3054.16 1841.97,3084.61 1797.62,3128.96 v3(1770.91,3128.96) 1494.61,3128.96 1403.94,3219.62 1403.94,3518.34 1531.44,3645.85 1691.9,3645.85 1692.03,3645.98 1701.25,3645.98 1765.34,3710.07 v3(1765.34,3750.45) 1782.61,3767.72 1782.61,4034.79 v3(1753.27,4064.13) 1527.96,4064.13 1386.86,4205.23 1386.86,4478.27 1463.72,4555.13 1753.82,4555.13 1839.01,4640.32 1839.01,4671.26 v3(1838.78,4671.49) ; TP18.1@2508.73,6724.5 2482.3,6724.5 2319.28,6561.48 2319.28,6067.17 1891.01,5638.9 1862.42,5638.9 v3(1827.03,5603.51) 1796.81,5603.51 1763.04,5569.74 1467.81,5569.74 1338.88,5440.81 1338.88,5210.94 1445.92,5103.9 1752.53,5103.9 1790.15,5066.27 1790.15,4810.33 1862.98,4737.51 1862.98,4695.68 ; v3(1838.78,4671.49) 1862.98,4695.68 ; v3(1838.78,4671.49) 1841.58,4671.49 1862.98,4692.88 1862.98,4695.68
  Bottom Layer w10: v3(1765.34,3750.45) 1781.34,3734.46 RZ30.2@1781.34,3678.28 ; RZ37.2@1770.85,3167.28 1770.85,3129.02 v3(1770.91,3128.96) ; RZ44.2@1825.64,2733.08 v3(1825.64,2767.94) ; v3(1827.03,5603.51) 1827.2,5603.34 RZ16.2@1827.2,5567.04 ; v3(1838.78,4671.49) 1839.01,4671.26 RZ9.2@1839.01,4638.63
SWEN_0: R50.2 RZ9.1 U1.21 | length 165.9
  Top Layer w7.87: R50.2@1839.01,4591.39 1841.39,4589.01 v3(1841.39,4567.01) U1.21@1841.39,4451.8
  Bottom Layer w7.87: RZ9.1@1839.01,4591.39 1841.39,4589.01 v3(1841.39,4567.01)
SWEN_1: R60.2 RZ16.1 U2.21 | length 154.1
  Top Layer w8: R60.2@1827.2,5519.8 v3(1827.2,5495.42) 1827.2,5430.1 1841.39,5415.91 U2.21@1841.39,5396
  Bottom Layer w8: v3(1827.2,5495.42) RZ16.1@1827.2,5519.8
SWEN_2: R65.2 RZ23.1 U3.21 | length 227.7
  Top Layer w8: RZ23.1@1753.27,4144.84 v3(1753.27,4174.86)
  Bottom Layer w8: R65.2@1753.27,4144.84 v3(1753.27,4174.86) 1753.27,4204.88 1790.54,4242.16 1827.31,4242.16 1841.39,4256.23 U3.21@1841.39,4284.48
SWEN_3: R70.2 RZ30.1 U4.21 | length 181.7
  Top Layer w8: R70.2@1781.34,3631.03 1781.34,3607.71 v3(1782.39,3606.65) 1782.39,3574.66 1794.7,3562.35 1811.89,3562.35 1840.69,3533.54 U4.21@1840.69,3508.81
  Bottom Layer w10: RZ30.1@1781.34,3631.03 1781.34,3607.71 v3(1782.39,3606.65)
SWEN_4: R75.2 RZ37.1 U5.21 | length 173.9
  Top Layer w8: R75.2@1770.85,3214.52 v3(1770.85,3248.84)
  Bottom Layer w8: RZ37.1@1770.85,3214.52 v3(1770.85,3248.84) 1786.9,3248.84 1811.8,3273.75 1828.7,3273.75 1840.69,3285.75 U5.21@1840.69,3305.85
SWEN_5: R80.2 RZ44.1 U6.21 | length 172.7
  Top Layer w8: R80.2@1825.64,2685.83 1815.91,2676.11 v3(1815.91,2654.15) 1815.91,2610.41 1841.39,2584.94 U6.21@1841.39,2563.41
  Bottom Layer w8: v3(1815.91,2654.15) 1825.64,2663.88 RZ44.1@1825.64,2685.83
TEMP: CTEMP1.1 RZ8.2 RZ15.2 RZ22.2 RZ29.2 RZ36.2 RZ43.2 TP19.1 | length 8529.7
  Top Layer w8: v3(1906.22,5023.9) RZ15.2@1906.22,5054.74
  Top Layer w10: v3(1882.14,2183.9) RZ43.2@1882.14,2216.11 ; v3(1898.45,4065.49) RZ8.2@1898.45,4097.6 ; RZ29.2@1954.58,3167.28 1954.58,3139.32 v3(1975,3118.9)
  L7-INT 2 w8: TP19.1@1819.84,7074.5 1917.1,7171.76 2488.55,7171.76 2617.07,7043.24 2617.07,6650.1 2535.62,6568.65 2402.92,6568.65 2364.03,6529.76 2364.03,5627.45 2402.92,5588.56 2402.92,5251.23 2261.51,5109.82 1967,5109.82 1906.22,5049.04 v3(1906.22,5023.9) 1934.13,4995.98 v3(1934.13,4678.9) 2041.78,4571.25 2197.99,4571.25 2290.09,4479.15 2290.09,4219.53 2232.01,4161.45 1950.92,4161.45 1898.45,4108.97 v3(1898.45,4065.49) 1932.65,4031.28 1932.65,3771.94 v3(1876.59,3715.88) 1876.59,3654.7 1899.96,3631.33 2029.95,3631.33 2078.84,3582.44 2252.55,3582.44 2289.28,3545.72 2289.28,3290.34 2231.88,3232.93 2021.84,3232.93 1975,3186.1 v3(1975,3118.9) 1975,3118.58 2064.67,3028.91 2278.37,3028.91 2420.72,2886.56 2420.72,2415.29 2219.33,2213.9 1912.14,2213.9 v3(1882.14,2183.9)
  Bottom Layer w10: RZ36.2@1876.59,3678.28 v3(1876.59,3715.88) ; CTEMP1.1@1894.84,4023.9 1898.45,4027.5 v3(1898.45,4065.49) ; RZ22.2@1934.13,4638.63 v3(1934.13,4678.9)
TEMP_0: RZ8.1 U1.5 | length 126
  Top Layer w7.87: U1.5@1888.63,4266.76 1888.63,4200.65 1898.45,4190.84 RZ8.1@1898.45,4144.84
TEMP_1: RZ15.1 U2.5 | length 116.3
  Top Layer w8: U2.5@1888.63,5210.96 1888.63,5119.57 RZ15.1@1906.22,5101.98
TEMP_2: RZ22.1 U3.5 | length 140.7
  Bottom Layer w8: U3.5@1888.63,4469.52 1888.63,4493.13 1934.13,4538.62 v3(1934.13,4557.5) RZ22.1@1934.13,4591.39
TEMP_3: RZ29.1 U4.5 | length 136.8
  Top Layer w8: U4.5@1887.94,3323.77 1887.94,3291.68 1942.77,3236.85 1942.77,3226.33 RZ29.1@1954.58,3214.52
TEMP_4: RZ36.1 U5.5 | length 145.1
  Bottom Layer w8: RZ36.1@1876.59,3631.33 RZ36.1@1876.59,3631.03 1876.59,3586.48 1887.94,3575.14 U5.5@1887.94,3490.89
TEMP_5: RZ43.1 U6.5 | length 117.7
  Top Layer w8: RZ43.1@1882.14,2263.36 1882.14,2317.56 1888.63,2324.05 U6.5@1888.63,2378.37
VDD: C25.1 R41.2 U1.22 | length 66.4
  Bottom Layer w15: R41.2@1746.27,4495.01 1749.9,4498.64 v3(1811.18,4498.64)
VDD_1: C52.2 R59.1 U2.22 | length 202.8
  Top Layer w15: R59.1@1686.42,5504.76 1696.78,5494.41 C52.2@1753.35,5494.41 1803.95,5443.81 1803.95,5426.21 1820.97,5409.19 U2.22@1820.97,5390.83
VDD_2: C56.2 R64.1 U3.22 | length 190.8
  Top Layer w15: C56.2@1695.95,4209.44 v3(1728.55,4209.44)
  Bottom Layer w15: R64.1@1695.95,4209.44 v3(1728.55,4209.44) 1808.76,4289.65 U3.22@1820.97,4289.65
VDD_3: C60.2 R69.1 U4.22 | length 175.2
  Top Layer w15: C60.2@1725.62,3606.65 1725.62,3565.71 R69.1@1748.06,3543.27 1801.79,3543.27 1820.97,3524.09 U4.22@1820.97,3502.44
VDD_4: C64.2 R74.1 U5.22 | length 170.1
  Bottom Layer w12: C64.2@1717.14,3222.3 R74.1@1717.14,3273.9 1728.48,3285.24 1794.49,3285.24 U5.22@1820.27,3311.02
VDD_5: C68.2 R79.1 U6.22 | length 152.1
  Top Layer w15: C68.2@1735.88,2606.56 v2(1772.21,2606.56) 1790.8,2606.56 1820.97,2576.4 U6.22@1820.97,2558.24
  Bottom Layer w15: R79.1@1735.88,2606.56 v2(1772.21,2606.56)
